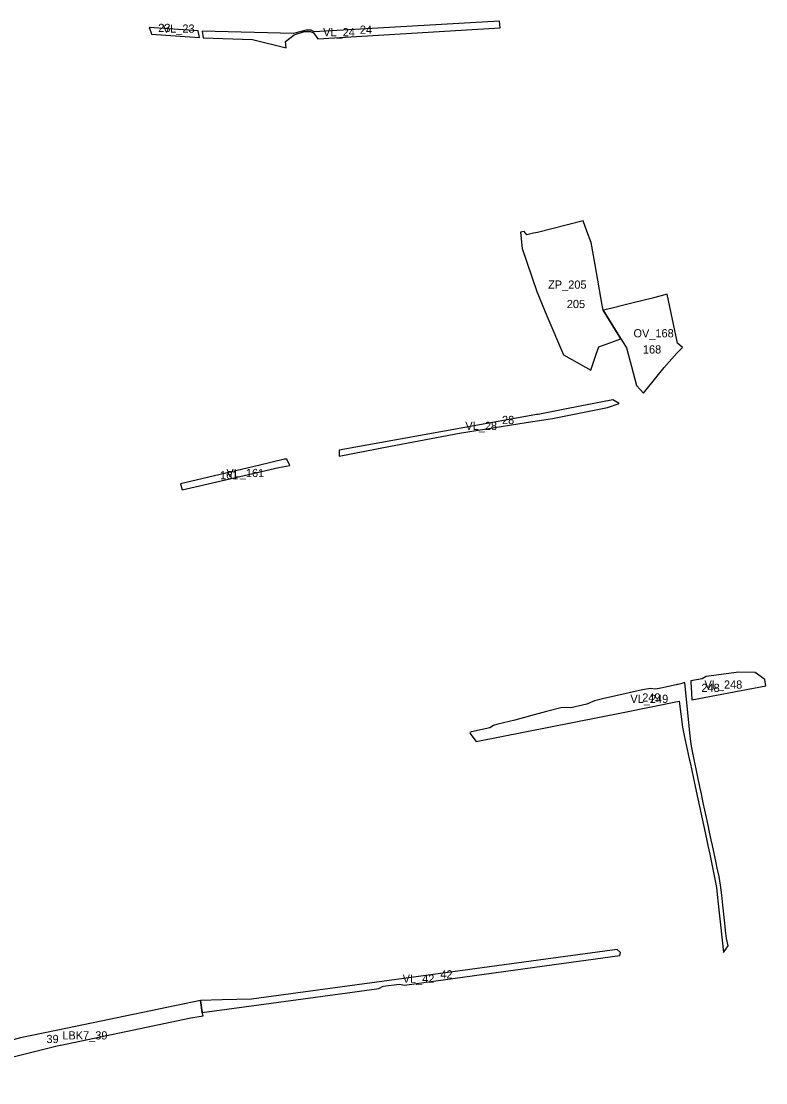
# Model space of a CAD drawing. Extents: x -521939 to -518034, y -1194984 to -1189555.
# Drawn here: x -520815 to -519907, y -1192796 to -1191501 of the extents above; entities that cross this region are included whole.
import ezdxf

# ---------------------------------------------------------------- set-up
doc = ezdxf.new("R2010")
doc.units = 0
for name, color, linetype in [('96120023', 7, 'Continuous'), ('96140023', 7, 'Continuous'), ('ID VPO', 7, 'Continuous'), ('ID VPS', 7, 'Continuous')]:
    doc.layers.add(name, color=color, linetype=linetype)

msp = doc.modelspace()

# ---------------------------------------------------------------- linework, layer by layer
at = {"layer": '96120023'}
for points in [[(-520231.3, -1191500.76), (-520281.01, -1191503.56), (-520457.48, -1191513.5), (-520461.23, -1191511.82), (-520467.01, -1191511.47), (-520482.44, -1191515.66), (-520594.1, -1191512.73)], [(-520230.44, -1191508.92), (-520231.3, -1191500.76)], [(-520658.4, -1191508.21), (-520656.53, -1191513.73), (-520655.62, -1191516.43)], [(-520598.71, -1191512.42), (-520658.4, -1191508.21)], [(-520597.37, -1191520.53), (-520598.71, -1191512.42)], [(-520594.1, -1191512.73), (-520592.74, -1191520.81)], [(-520491.32, -1191533.14), (-520492.29, -1191525.29), (-520481.62, -1191517.42), (-520469.32, -1191513.47), (-520461.73, -1191513.47), (-520458.29, -1191515), (-520452.73, -1191522.22)], [(-520452.73, -1191522.22), (-520264.87, -1191510.98), (-520230.44, -1191508.92)], [(-520655.62, -1191516.43), (-520597.37, -1191520.53)], [(-520592.74, -1191520.81), (-520532.56, -1191523.11)], [(-520532.56, -1191523.11), (-520491.32, -1191533.14)], [(-520129.36, -1191744.38), (-520185.24, -1191758.27)], [(-520124.76, -1191756.84), (-520129.36, -1191744.38)], [(-520201.52, -1191757.27), (-520205.83, -1191758.24)], [(-520205.83, -1191758.24), (-520203.95, -1191777.85)], [(-520189.75, -1191759.39), (-520197.9, -1191761.48), (-520201.52, -1191757.27)], [(-520185.24, -1191758.27), (-520189.75, -1191759.39)], [(-520119.69, -1191770.62), (-520124.76, -1191756.84)], [(-520114.94, -1191797.7), (-520119.69, -1191770.62)], [(-520203.95, -1191777.85), (-520185.99, -1191830.46)], [(-520106.18, -1191847.24), (-520114.94, -1191797.7)], [(-520185.99, -1191830.46), (-520173.54, -1191860.15)], [(-520027.04, -1191833.79), (-520044.99, -1191838.35), (-520068.5, -1191844.29)], [(-520014.4, -1191893.4), (-520027.04, -1191833.79)], [(-520105.09, -1191853.21), (-520106.18, -1191847.24)], [(-520078.22, -1191846.75), (-520095.58, -1191851.22)], [(-520068.5, -1191844.29), (-520078.22, -1191846.75)], [(-520173.54, -1191860.15), (-520153.55, -1191907.81)], [(-520095.58, -1191851.22), (-520105.09, -1191853.21)], [(-520105.09, -1191853.21), (-520083.3, -1191887.96)], [(-520083.3, -1191887.96), (-520105.09, -1191853.21)], [(-520110.14, -1191897.75), (-520096.72, -1191892.86), (-520083.3, -1191887.96)], [(-520083.3, -1191887.96), (-520077.68, -1191896.92)], [(-520113.38, -1191906.91), (-520110.14, -1191897.75)], [(-520077.68, -1191896.92), (-520076.36, -1191899.02), (-520070.28, -1191922.07), (-520064.19, -1191945.12), (-520060.07, -1191949.85), (-520055.94, -1191954.58)], [(-520030.81, -1191922.99), (-520015.01, -1191905.83), (-520008.2, -1191898.59)], [(-520008.2, -1191898.59), (-520014.4, -1191893.4)], [(-520153.55, -1191907.81), (-520120.2, -1191926.19)], [(-520120.2, -1191926.19), (-520113.38, -1191906.91)], [(-520055.94, -1191954.58), (-520052.53, -1191950.29), (-520030.81, -1191922.99)], [(-520093.1, -1191962.36), (-520149.53, -1191973.51), (-520184.43, -1191980.26)], [(-520085.46, -1191967.04), (-520093.1, -1191962.36)], [(-520166.67, -1191985.2), (-520099.84, -1191971.93), (-520085.46, -1191967.04)], [(-520188.39, -1191981.03), (-520249.07, -1191991.95), (-520426.72, -1192023.92)], [(-520280.31, -1192003.2), (-520198.94, -1191990.1)], [(-520198.94, -1191990.1), (-520177.25, -1191986.81)], [(-520184.43, -1191980.26), (-520186.17, -1191980.57), (-520188.39, -1191981.03)], [(-520177.25, -1191986.81), (-520166.67, -1191985.2)], [(-520364.5, -1192019.1), (-520280.31, -1192003.2)], [(-520426.95, -1192031.34), (-520364.5, -1192019.1)], [(-520426.72, -1192023.92), (-520426.95, -1192031.34)], [(-520493.41, -1192035.03), (-520525.18, -1192042.5), (-520620.5, -1192064.91)], [(-520500.53, -1192045.04), (-520487.08, -1192042.46)], [(-520487.08, -1192042.46), (-520490.69, -1192035.01), (-520493.41, -1192035.03)], [(-520618.37, -1192072.35), (-520500.53, -1192045.04)], [(-520620.5, -1192064.91), (-520618.37, -1192072.35)], [(-519984.39, -1192302.69), (-519998.15, -1192305.25)], [(-519939.67, -1192294.88), (-519979.44, -1192300.11), (-519984.39, -1192302.69)], [(-519919.82, -1192295.13), (-519939.67, -1192294.88)], [(-519907.89, -1192303.65), (-519919.82, -1192295.13)], [(-520057.05, -1192316.46), (-520105.95, -1192327.26)], [(-520047.46, -1192314.76), (-520057.05, -1192316.46)], [(-520041.17, -1192315.39), (-520047.46, -1192314.76)], [(-520034.73, -1192314.14), (-520041.17, -1192315.39)], [(-520015.86, -1192310.06), (-520034.73, -1192314.14)], [(-520014.95, -1192309.86), (-520015.86, -1192310.06)], [(-520010.2, -1192308.83), (-520013.73, -1192309.6), (-520014.95, -1192309.86)], [(-520009.17, -1192308.52), (-520010.2, -1192308.83)], [(-520005.28, -1192307.33), (-520009.17, -1192308.52)], [(-519998.98, -1192372.94), (-520005.28, -1192307.33)], [(-519998.15, -1192305.25), (-519998.28, -1192306.62)], [(-519998.28, -1192306.62), (-519997.42, -1192320.41)], [(-519996.92, -1192328.48), (-519906.74, -1192311.24)], [(-519906.74, -1192311.24), (-519907.89, -1192303.65)], [(-520115.51, -1192329.52), (-520124.86, -1192333.87)], [(-520105.95, -1192327.26), (-520115.51, -1192329.52)], [(-519997.42, -1192320.41), (-519996.92, -1192328.48)], [(-520154.82, -1192337.98), (-520174.07, -1192342.77)], [(-520144.55, -1192338.08), (-520154.82, -1192337.98)], [(-520124.86, -1192333.87), (-520144.55, -1192338.08)], [(-520080.47, -1192343.75), (-520012.45, -1192330.19)], [(-520012.45, -1192330.19), (-520008.24, -1192361.89)], [(-520259.75, -1192379.49), (-520080.47, -1192343.75)], [(-520212.74, -1192353.2), (-520233.56, -1192358.34)], [(-520193.4, -1192348.01), (-520212.74, -1192353.2)], [(-520174.07, -1192342.77), (-520193.4, -1192348.01)], [(-520265.64, -1192367.66), (-520267.65, -1192368.23)], [(-520267.65, -1192368.23), (-520267.03, -1192369.46), (-520264.96, -1192372.31), (-520259.75, -1192379.49)], [(-520243.36, -1192362.72), (-520265.64, -1192367.66)], [(-520238.84, -1192359.64), (-520243.36, -1192362.72)], [(-520233.56, -1192358.34), (-520238.84, -1192359.64)], [(-520008.24, -1192361.89), (-520006.07, -1192371.92)], [(-520006.07, -1192371.92), (-519999.94, -1192400.62)], [(-519997.31, -1192384.9), (-519998.98, -1192372.94)], [(-519994.19, -1192401.25), (-519997.31, -1192384.9)], [(-519999.94, -1192400.62), (-519999.03, -1192404.87)], [(-519999.03, -1192404.87), (-519994.83, -1192424.53)], [(-519991.79, -1192412.45), (-519994.19, -1192401.25)], [(-519989.57, -1192422.89), (-519991.79, -1192412.45)], [(-519994.83, -1192424.53), (-519992.75, -1192434.33)], [(-519987.07, -1192434.66), (-519989.57, -1192422.89)], [(-519992.75, -1192434.33), (-519979.09, -1192498.16)], [(-519985.25, -1192443.1), (-519987.07, -1192434.66)], [(-519982.92, -1192453.96), (-519985.25, -1192443.1)], [(-519981, -1192462.94), (-519982.92, -1192453.96)], [(-519979.09, -1192471.82), (-519981, -1192462.94)], [(-519977.05, -1192481.41), (-519979.09, -1192471.82)], [(-519975.18, -1192490), (-519977.05, -1192481.41)], [(-519973.23, -1192499.19), (-519975.18, -1192490)], [(-519979.09, -1192498.16), (-519977.31, -1192506.28)], [(-519977.31, -1192506.28), (-519975.1, -1192516.62)], [(-519971.66, -1192506.17), (-519973.23, -1192499.19)], [(-519967.19, -1192527.44), (-519971.66, -1192506.17)], [(-519975.1, -1192516.62), (-519966.68, -1192557.39), (-519965.84, -1192566)], [(-519965.8, -1192533.95), (-519967.19, -1192527.44)], [(-519963.65, -1192543.99), (-519965.8, -1192533.95)], [(-519961.77, -1192554.51), (-519963.65, -1192543.99)], [(-519960.25, -1192566.55), (-519961.77, -1192554.51)], [(-519965.84, -1192566), (-519964.65, -1192577.41)], [(-519958.97, -1192578.79), (-519960.25, -1192566.55)], [(-519964.65, -1192577.41), (-519961.87, -1192602.8)], [(-519955.64, -1192609.73), (-519956.62, -1192600.81), (-519958.97, -1192578.79)], [(-519961.87, -1192602.8), (-519958.27, -1192636.72)], [(-519954.63, -1192619.45), (-519955.64, -1192609.73)], [(-519952.4, -1192628.52), (-519954.63, -1192619.45)], [(-520176.35, -1192652.97), (-520084.86, -1192640.48), (-520083.77, -1192636.81)], [(-520088.02, -1192632.83), (-520175.03, -1192644.71)], [(-520083.77, -1192636.81), (-520088.02, -1192632.83)], [(-519958.27, -1192636.72), (-519952.4, -1192628.52)], [(-520175.03, -1192644.71), (-520356.96, -1192669.55), (-520533.69, -1192693.68), (-520569.38, -1192694.51)], [(-520347.39, -1192676.32), (-520176.35, -1192652.97)], [(-520416.9, -1192685.81), (-520378.59, -1192680.58), (-520373.25, -1192677.83)], [(-520373.25, -1192677.83), (-520353.27, -1192675.1), (-520347.39, -1192676.32)], [(-520593.8, -1192709.96), (-520416.9, -1192685.81)], [(-520569.38, -1192694.51), (-520596.04, -1192695.13)], [(-520596.04, -1192695.13), (-520593.8, -1192709.96)]]:
    msp.add_lwpolyline(points, dxfattribs=at)
at = {"layer": '96140023'}
for points in [[(-520596.04, -1192695.13), (-520758.3, -1192728.9), (-520815.45, -1192740.8), (-520834.88, -1192746.05)], [(-520593.8, -1192709.96), (-520596.04, -1192695.13)], [(-520766.41, -1192749.65), (-520607.67, -1192716.44)], [(-520607.67, -1192716.44), (-520592.85, -1192713.96)], [(-520592.85, -1192713.96), (-520593.8, -1192709.96)], [(-520930.47, -1192795.56), (-520873.66, -1192776.25), (-520770.76, -1192750.7)], [(-520770.76, -1192750.7), (-520767.25, -1192749.83), (-520766.41, -1192749.65)]]:
    msp.add_lwpolyline(points, dxfattribs=at)

# ---------------------------------------------------------------- texts
at = {"layer": '96120023'}
for s, rotation, p in [('VL_23', 360, (-520641.87, -1191514.77)), ('VL_24', 360, (-520446.45, -1191519.14)), ('ZP_205', 360, (-520172.1, -1191827)), ('OV_168', 360, (-520068.03, -1191886.37)), ('VL_28', 360, (-520273.07, -1191999.37)), ('VL_161', 0, (-520564.45, -1192056.79)), ('VL_248', 360, (-519981.5, -1192314.86)), ('VL_249', 0, (-520071.78, -1192332.29)), ('VL_42', 0, (-520349.47, -1192673.62))]:
    msp.add_text(s, height=10, rotation=rotation, dxfattribs=at).set_placement(p)
at = {"layer": '96140023'}
msp.add_text('LBK7_39', height=10, rotation=0, dxfattribs=at).set_placement((-520764.46, -1192742.73))
at = {"layer": 'ID VPO'}
msp.add_text('39', height=10, rotation=0, dxfattribs=at).set_placement((-520783.82, -1192747.13))
at = {"layer": 'ID VPS'}
for s, rotation, p in [('23', 360, (-520647.52, -1191513.93)), ('24', 0, (-520401.68, -1191516.08)), ('205', 360, (-520149.34, -1191850.67)), ('168', 360, (-520056.55, -1191906.06)), ('28', 0, (-520228.33, -1191992.13)), ('161', 360, (-520572.14, -1192059.37)), ('248', 360, (-519985.2, -1192318.89)), ('249', 0, (-520057.37, -1192330.59)), ('42', 0, (-520303.47, -1192668.31))]:
    msp.add_text(s, height=10, rotation=rotation, dxfattribs=at).set_placement(p)

doc.saveas('drawing.dxf')
